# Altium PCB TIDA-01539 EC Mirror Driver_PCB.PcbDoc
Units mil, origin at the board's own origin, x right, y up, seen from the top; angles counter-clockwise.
Board outline 2800 x 1700 mil, 2 copper layers (Top Layer, Bottom Layer), stack 62 mil thick; 45 components, 15 nets, 162 pads, 47 vias.
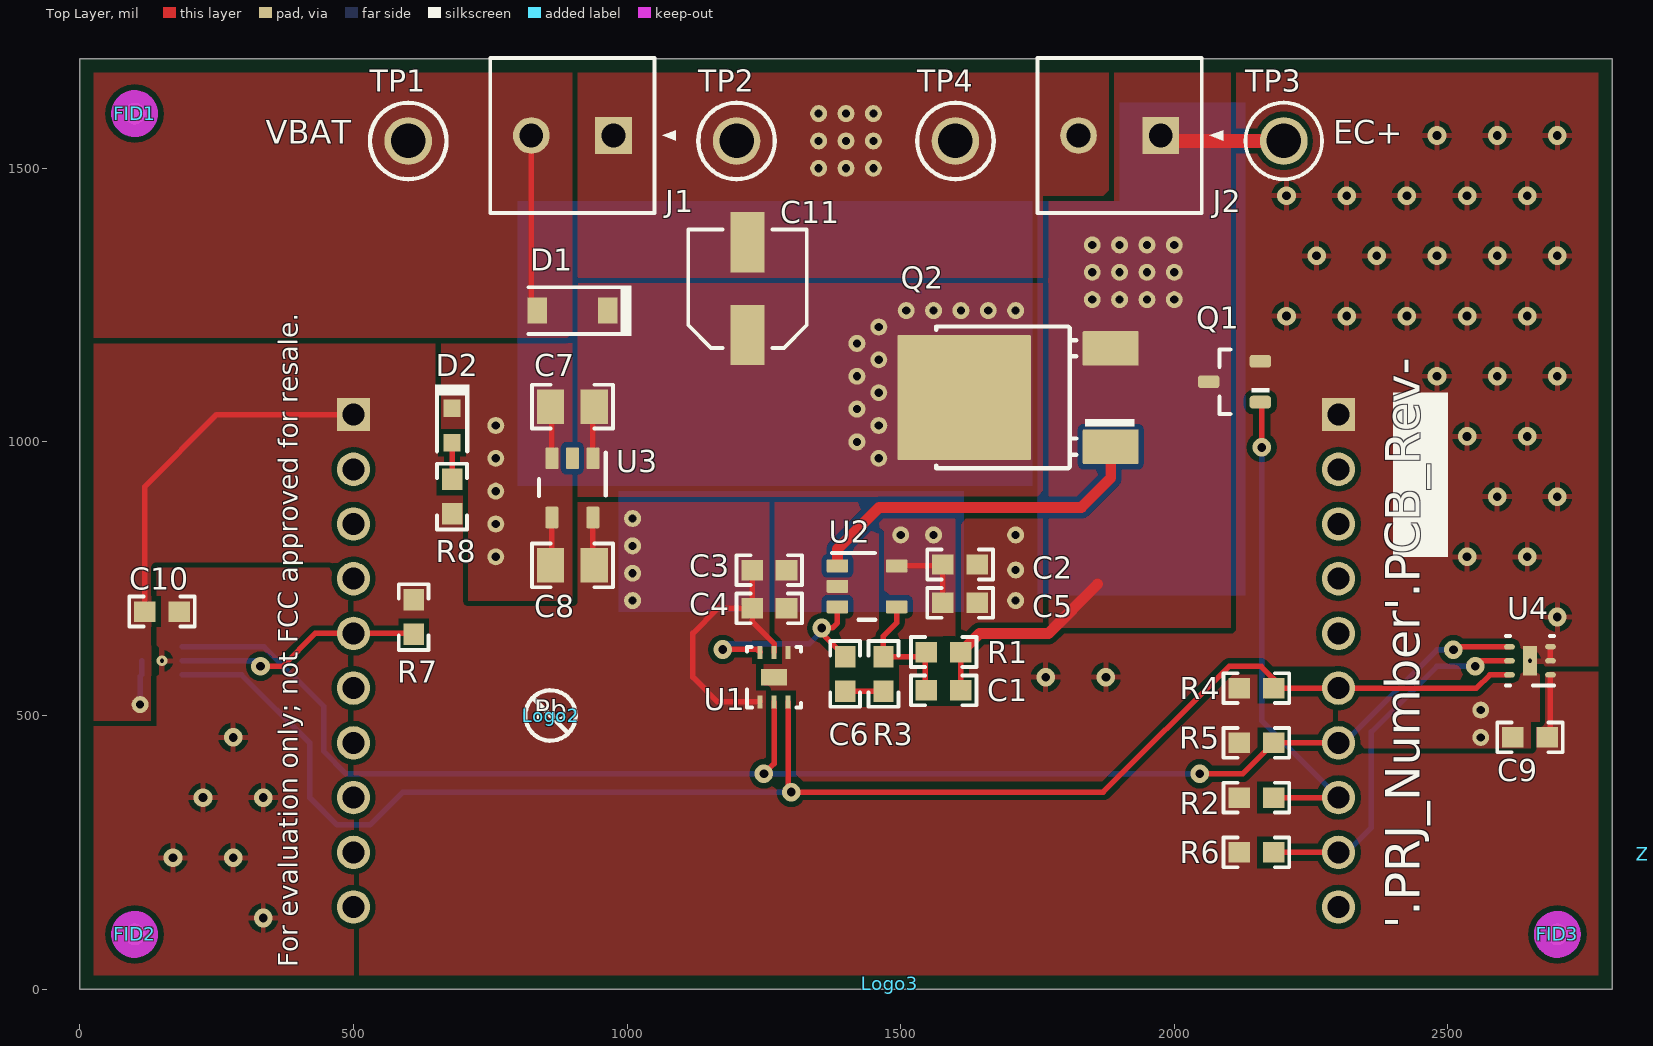
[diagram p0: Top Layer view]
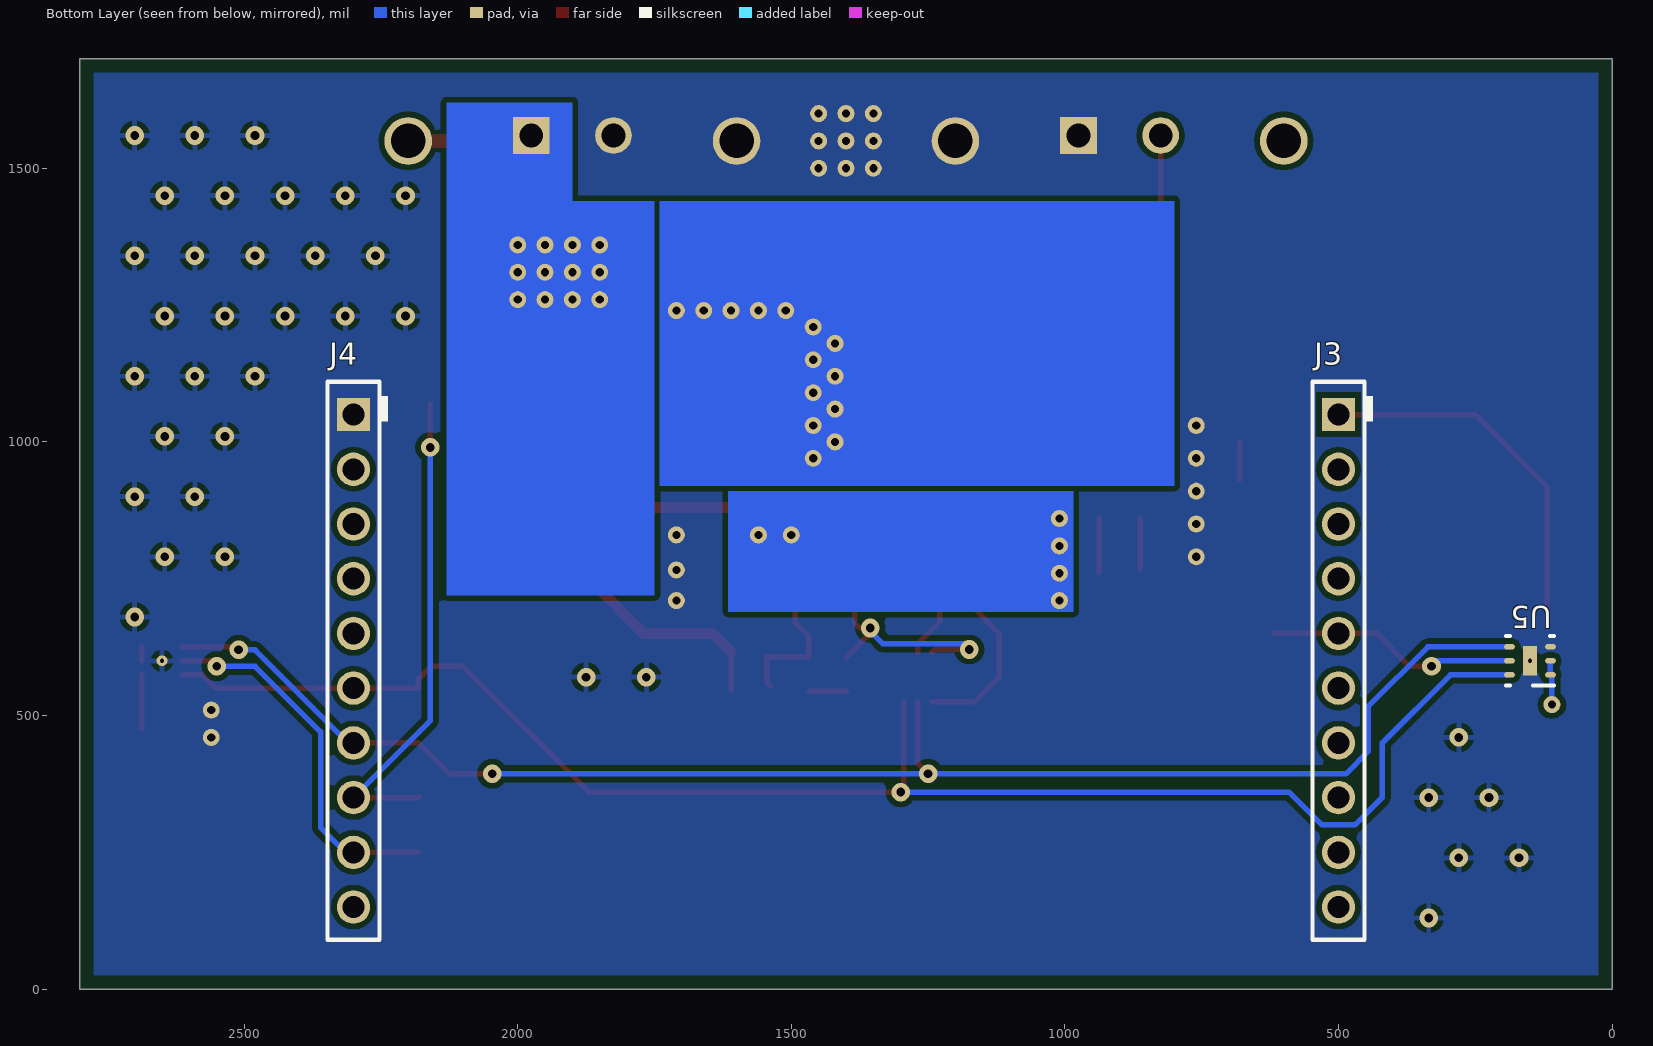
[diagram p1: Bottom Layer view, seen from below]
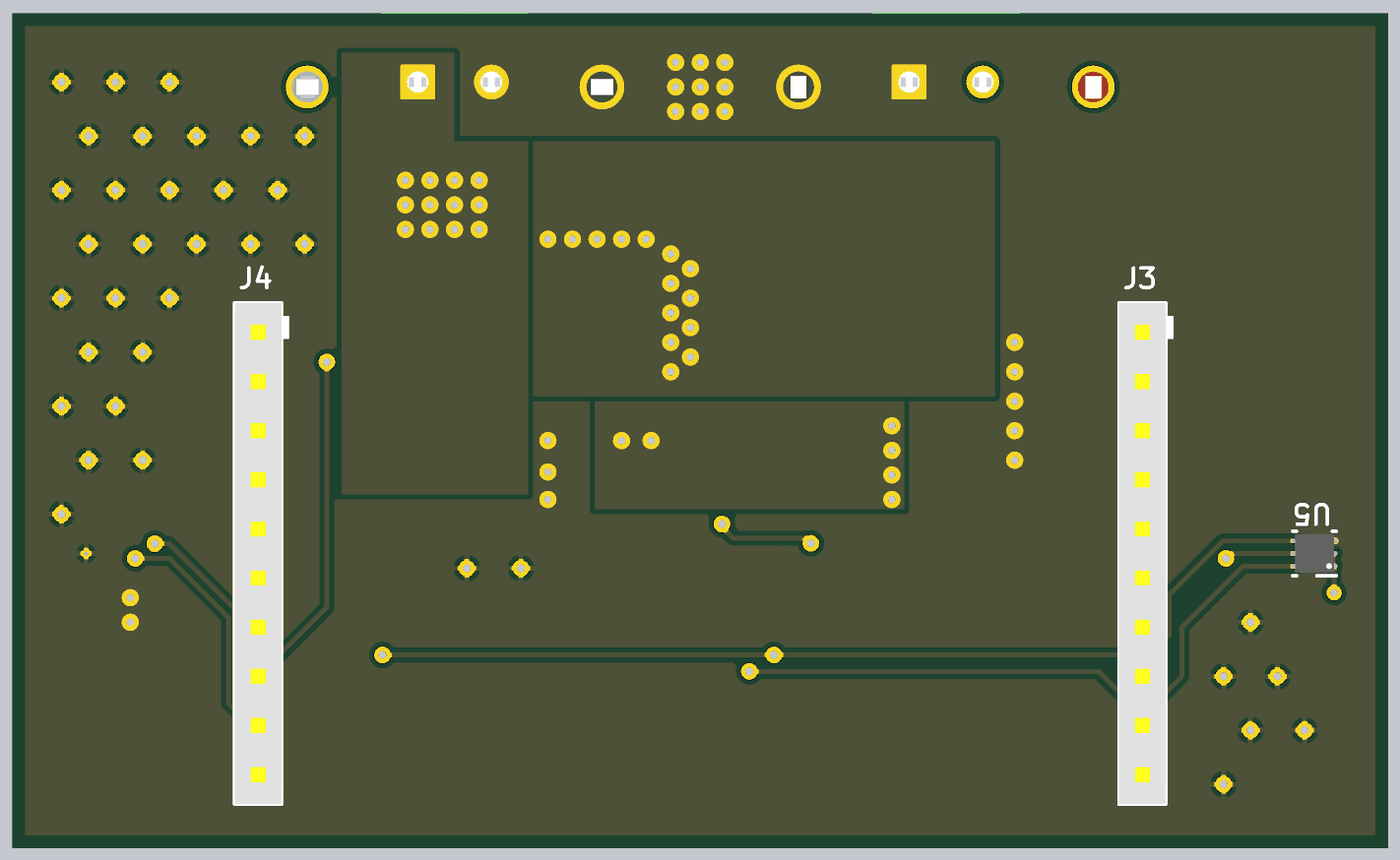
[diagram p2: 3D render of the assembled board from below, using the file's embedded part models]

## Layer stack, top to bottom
Top Solder: solder mask 0.4, Solder Resist, Dk 3.5
Top Layer: signal copper 1.4
Dielectric1: core 59.2, FR-4, Dk 4.8
Bottom Layer: signal copper 1.4
Bottom Solder: solder mask 0.4, Solder Resist, Dk 3.5

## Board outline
0,0 2800,0 2800,1700 0,1700

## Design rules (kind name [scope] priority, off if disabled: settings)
AcuteAngle [All] p1: minimum=4.50000000000000E+0001 checktracksonly=FALSE
AssemblyTestPointUsage [All] p1: valid=2
BoardOutlineClearance BoardOutlineClearance_MountingHoles [OnCopper and InComponentClass('Mounting Holes')] p1: gap=40 ignorepadtopadclearanceinfootprint=FALSE
BoardOutlineClearance BoardOutlineClearance_Poly [OnCopper and IsPoly] p2: gap=25 ignorepadtopadclearanceinfootprint=FALSE
BoardOutlineClearance [OnCopper and Not InComponentClass('Logo') and not InComponentClass('FiducialMark') and not InRegion(1000,500,4000,800) and not InPoly] p3: gap=75 ignorepadtopadclearanceinfootprint=FALSE
Clearance Clearance_Keepouts [((IsTrack Or IsArc) And Not InPoly) And IsFree and IsKeepOut vs ((IsTrack Or IsArc) And Not InPoly) And IsFree and IsKeepOut] p1: gap=0 ignorepadtopadclearanceinfootprint=FALSE
Clearance Clearance_Poly [InPolygon] p2: gap=10 ignorepadtopadclearanceinfootprint=FALSE
Clearance Clearance_FiducialMark [IsKeepOut and InComponentClass('FiducialMark') vs IsPad and InComponentClass('FiducialMark')] p3: gap=0 ignorepadtopadclearanceinfootprint=FALSE
Clearance [All] p4: gap=7.87 ignorepadtopadclearanceinfootprint=FALSE except(0: Arc-Hole Track-Hole SMDPad-Hole THPad-Hole Via-Hole Fill-Hole Poly-Hole Region-Hole Text-Hole)
ComponentClearance ComponentClearance_MountingHoles_FiducialMarks [InComponentClass('Mounting Holes') vs InComponentClass('FiducialMark')] p1: gap=50 collisioncheckmode=3 verticalgap=10 showdistances=FALSE
ComponentClearance ComponentClearance_Shunt [InComponentClass('Header') vs InComponentClass('Shunt')] p2: gap=0 collisioncheckmode=3 verticalgap=0 showdistances=FALSE
ComponentClearance ComponentClearance_Logo [InComponentClass('Logo')] p3: gap=50 collisioncheckmode=3 verticalgap=10 showdistances=FALSE
ComponentClearance ComponentClearance_ScrewToNut [(HasFootprint('NY PMS 440 0025 PH')) vs (HasFootprint('Keystone_1902C'))] p4: gap=5 collisioncheckmode=3 verticalgap=10 showdistances=FALSE
ComponentClearance ComponentClearance_MountingHoles [InComponentClass('Mounting Holes')] p5: gap=250 collisioncheckmode=3 verticalgap=100000 showdistances=FALSE
ComponentClearance ComponentClearance_SmallPassives [HasFootprint('0201*') or HasFootprint('0402*') or HasFootprint('0508') or HasFootprint('0603*') or HasFootprint('0612') or HasFootprint('0805*') or HasFootprint('0815*') or HasFootprint('0830*') or HasFootprint('1206*') or HasFootprint('1210*') or HasFootprint('1808*') or HasFootprint('1812*') or HasFootprint('1825*') or HasFootprint('2010*') or HasFootprint('2220*') or HasFootprint('2225*') or HasFootprint('2512*') or HasFootprint('2728*') or HasFootprint('3518*') vs HasFootprint('0201*') or HasFootprint('0402*') or HasFootprint('0508') or HasFootprint('0603*') or HasFootprint('0612') or HasFootprint('0805*') or HasFootprint('0815*') or HasFootprint('0830*') or HasFootprint('1206*') or HasFootprint('1210*') or HasFootprint('1808*') or HasFootprint('1812*') or HasFootprint('1825*') or HasFootprint('2010*') or HasFootprint('2220*') or HasFootprint('2225*') or HasFootprint('2512*') or HasFootprint('2728*') or HasFootprint('3518*')] p6: gap=14.96 collisioncheckmode=3 verticalgap=10 showdistances=FALSE
ComponentClearance ComponentClearance_THtoSMT [IsThruComponent vs IsSMTComponent] p7: gap=40 collisioncheckmode=3 verticalgap=30 showdistances=FALSE
ComponentClearance ComponentClearance_THtoTH [IsThruComponent vs IsThruComponent] p8: gap=30 collisioncheckmode=3 verticalgap=30 showdistances=FALSE
ComponentClearance [All] p9: gap=30 collisioncheckmode=3 verticalgap=10 showdistances=FALSE
DiffPairsRouting [All] p1: maxlimit=100 minlimit=10 mostfreqgap=10 toplayer_minwidth=15 toplayer_maxwidth=15 toplayer_prefwidth=15 bottomlayer_minwidth=15 bottomlayer_maxwidth=15 bottomlayer_prefwidth=15 maxuncoupledlength=1000
FabricationTestPointUsage TestPointUsage [All] p1: valid=2 allowmultiple=FALSE
FabricationTestpoint Testpoint [All] p1: side=3 testpointundercomponent=TRUE minsize=40 maxsize=100 preferedsize=60 minholesize=0 maxholesize=40 preferedholesize=32 testpointgrid=1 allowsidetop=TRUE allowsidebottom=TRUE usegrid=TRUE gridtolerance=0.01
FanoutControl Fanout_LCC [IsLCC] p1: bgadir=Out bgaviamode=Centered fanoutstyle=Auto fanoutdirection=Alternating viagrid=1 // Fanout_LCC (Default Rule)
FanoutControl Fanout_BGA [IsBGA] p2: bgadir=Out bgaviamode=Centered fanoutstyle=Auto fanoutdirection=Alternating viagrid=1 // Fanout_BGA (Default Rule)
FanoutControl Fanout_Default [All] p4: bgadir=Out bgaviamode=Centered fanoutstyle=Auto fanoutdirection=Alternating viagrid=1 // Fanout_Default (Default Rule)
FanoutControl Fanout_Small [(CompPinCount < 5)] p5: bgadir=Out bgaviamode=Centered fanoutstyle=Auto fanoutdirection=OutThenIn viagrid=1 // Fanout_Small (Default Rule)
HoleSize [All] p1: absolutevalues=TRUE maxlimit=251 minlimit=7.87 maxpercent=80.000 minpercent=20.000
MinimumAnnularRing MinimumAnnularRing_ThermalPadVias [IsVia and InAnyComponent] p1: minimumring=5.91
MinimumAnnularRing [All] p2: minimumring=8
MinimumSolderMaskSliver MinimumSolderMaskSliver_Logo [InComponentClass('Logo') vs InComponentClass('Logo')] p1: minsoldermaskwidth=0.7
MinimumSolderMaskSliver [All] p2: minsoldermaskwidth=3.94
PlaneConnect [All] p1: planeconnectstyle=Direct reliefexpansion=10 reliefentries=4 reliefconductorwidth=10 reliefairgap=10
PolygonConnect [All] p1: thpad.connectstyle=Direct thpad.reliefconductorwidth=10 thpad.reliefentries=4 thpad.polygonreliefangle="90 Angle" thpad.airgapwidth=10 smdpad.connectstyle=Direct smdpad.reliefconductorwidth=10 smdpad.reliefentries=4 smdpad.polygonreliefangle="90 Angle" smdpad.airgapwidth=10 via.connectstyle=Relief via.reliefconductorwidth=10 via.reliefentries=4 via.polygonreliefangle="90 Angle" via.airgapwidth=10
RoutingVias ThermalPadVias [IsVia and InAnyComponent] p1: holewidth=7.87 width=19.68 viastyle="Through Hole" minholewidth=7.87 minwidth=19.68 maxholewidth=12.99 maxwidth=23.62
RoutingVias [All] p2: holewidth=16 width=34 viastyle="Through Hole" minholewidth=7.87 minwidth=26 maxholewidth=40 maxwidth=65
SilkToBoardRegionClearance [Not ((IsComment or IsDesignator) And (Hide <> 'False')) and not InRegion(1000,500,4000,800)] p1:
SilkToSilkClearance SilkToSilkClearance_Pb-FreeLogo [(HasFootprint('Pb-Free_Overlay_Medium') OR HasFootprint('Pb-Free_Overlay_Small')) vs (HasFootprint('Pb-Free_Overlay_Medium') OR HasFootprint('Pb-Free_Overlay_Small'))] p1: silktosilkclearance=0
SilkToSilkClearance [All] p2: silktosilkclearance=4
SilkToSolderMaskClearance SilkToComponentPadClearance [(IsPad or IsFill or IsRegion) and InAnycomponent] p1: minsilkscreentomaskgap=5 clearancetoexposedcopper=TRUE
SilkToSolderMaskClearance "Silk to Solder Mask Opening" [All] p2: minsilkscreentomaskgap=4 clearancetoexposedcopper=FALSE
SolderMaskExpansion [All] p1: expansion=1.97
Width [All] p1: maxlimit=100 minlimit=6 preferedwidth=10 checkconnectedcopper=TRUE
15 further rules are at their usual default settings.

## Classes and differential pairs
component class "TIDA-01539 EC Mirror Driver_EVM_Hardware": FID1 FID2 FID3 Logo2 Logo3 ZZ1 ZZ2 ZZ3 ZZ4
component class FiducialMark: FID1 FID2 FID3
component class AssemblyNote: ZZ1 ZZ2 ZZ3 ZZ4
component class "TIDA-01539 EC Mirror Driver_Main": C1 C2 C3 C4 C5 C6 C7 C8 C9 C10 C11 D1 D2 J1 J2 J3 J4 Q1 Q2 R1 R2 R3 R4 R5 R6 R7 R8 TP1 TP2 TP3 TP4 U1 U2 U3 U4 U5

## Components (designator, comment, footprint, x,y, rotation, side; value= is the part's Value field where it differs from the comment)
C1 "0603ZC100KAT2A" 0603 1578.5,545.96 r180 top value=10pF
C2 "GRM188Z71C475KE21D" 0603 1608.5,775.96 r0 top value=4.7uF
C3 "GCM188R71C104KA37J" 0603 1259.8,765.66 r0 top value=0.1uF
C4 "GRM188Z71C475KE21D" 0603 1259.8,695.66 r0 top value=4.7uF
C5 "GCM188R71C104KA37J" 0603 1608.5,705.96 r0 top value=0.1uF
C6 "GCM188R71H472KA37D" 0603 1398.5,575.96 r90 top value=4700pF
C7 "GCM21BR71C475KA73K" 0805_HV 900,1064.53 r180 top value=4.7uF
C8 "CGA4J3X7R1E225K125AB" 0805_HV 900,774.53 r180 top value=2.2uF
C9 "GCM188R71C104KA37J" 0603 2650,460 r180 top value=0.1uF
C10 "GCM188R71C104KA37J" 0603 150,690 r0 top value=0.1uF
C11 "EEE-FK1V220R" SM_RADIAL_C 1220,1280 r90 top value=22uF
D1 "1N5819HW-7-F" SOD-123 900,1240 r180 top value=40V
D2 "150060GS75000" WL-SMCW_GREEN 680,1030 r270 top value=Green
FID1 "Fiducial" Fiducial10-20 100,1600 r0 top
FID2 "Fiducial" Fiducial10-20 100,100 r0 top
FID3 "Fiducial" Fiducial10-20 2700,100 r0 top
J1 "1727010" PhoenixConact_1727010 900,1560 r180 top
J2 "1727010" PhoenixConact_1727010 1900,1560 r180 top
J3 "SSQ-110-23-F-S" Samtec_SSQ-110-03-x-S 500,600 r270 bottom
J4 "SSQ-110-23-F-S" Samtec_SSQ-110-03-x-S 2300,600 r270 bottom
Logo2 "Pb-Free Symbol" Pb-Free_Overlay_Small 860,500 r0 top
Logo3 "FCC disclaimer" FCC_disclaimer 1480,10 r0 top
Q1 "FMMT495TA" SOT-23 2110,1110 r180 top value="150 V"
Q2 "NJVMJD122T4G" DPAK 1749.93,1081.04 r180 top value="100 V"
R1 "RT0603DRE0710K1L" 0603 1578.5,615.96 r0 top value=10.1k
R2 "RC0603FR-074K7L" 0603 2150,350 r180 top value=4.70k
R3 "CRCW0603499RFKEA" 0603 1468.5,575.96 r90 top value=499
R4 "RMCF0603FT10K0" 0603 2150,550 r180 top value=10.0k
R5 "RMCF0603FT10K0" 0603 2150,450 r180 top value=10.0k
R6 "RMCF0603FT10K0" 0603 2150,250 r180 top value=10.0k
R7 "RMCF0603FT10K0" 0603 610,680 r90 top value=10.0k
R8 "RC0603FR-07470RL" 0603 680,900 r270 top value=470
TP1 "5010" Keystone5010 600,1550 r0 top
TP2 "5011" Keystone5011 1200,1550 r0 top
TP3 "5128" Keystone5128 2200,1550 r270 top
TP4 "5011" Keystone5011 1600,1550 r270 top
U1 "DAC101C081QISD/NOPB" NGF0006A 1268.5,570 r90 top
U2 "TLV316QDBVTQ1" DBV0005A_N 1438.5,735.96 r0 top
U3 "TPS7B6933QDBVRQ1" DBV0005A_N 900,916.01 r270 top
U4 "OPT3001IDNPRQ1" DNP0006A 2650,600 r180 top
U5 "OPT3001IDNPRQ1" DNP0006A 150,600 r0 bottom
ZZ1 "This Assembly Note is for PCB labels only" AssemblyNoteLabel 185,3938 r0 top
ZZ2 "This Assembly Note will show in the PcbDoc and associated outputs" AssemblyNote 3238,246 r90 top
ZZ3 "This Assembly Note will show in the PcbDoc and associated outputs" AssemblyNote 3058,246 r90 top
ZZ4 "This Assembly Note will show in the PcbDoc and associated outputs" AssemblyNote 2878,246 r90 top

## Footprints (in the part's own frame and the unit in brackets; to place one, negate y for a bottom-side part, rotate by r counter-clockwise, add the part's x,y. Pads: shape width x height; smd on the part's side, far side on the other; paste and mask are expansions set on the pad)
0603 [mm] "0603 from SM-752 data"
  rect 1x0.95 smd: 1(-0.8,0) 2(0.8,0)
  silkscreen extent -1.52,-0.69 1.52,0.69, body extent -0.87,-0.47 0.87,0.47, height 1
0805_HV [mil] "0805 with 30mil clearance between pads"
  rect 50x63 smd: 1(-40,0) 2(40,0)
  silkscreen extent -74,-40 74,40, body extent -43,-29 43,29, height 57
AssemblyNote [mil] "Assembly Note"
AssemblyNoteLabel [mil] "Assembly Note for PCB Labels"
DBV0005A_N [mm] "SOT23, 5-Leads, Body 2.9x1.6mm, Pitch 0.95mm, Lead Span 2.8mm, IPC Medium Density"
  rrect17% 1x0.6 smd: 1(-1.375,0.95) 2(-1.375,0) 3(-1.375,-0.95) 4(1.375,-0.95) 5(1.375,0.95)
  silkscreen extent -1.63,-1.55 0.38,1.55, body extent -1.42,-1.46 1.42,1.46, height 1.09
DNP0006A [mm] "DFN-6 2x2mm"
  oval 0.5x0.25 smd: 1(-0.95,0.65) 2(-0.95,0) 3(-0.95,-0.655) 4(0.95,-0.65) 5(0.95,0) 6(0.95,0.65)
  rect 0.65x1.35 smd paste-0.5: 7(0,0)
  silkscreen extent -1.12,-1.15 1.12,1.15, body extent -1,-1 1,1, height 0.64
DPAK [mm] "D-PAK, 3-Pads, Body 6.22x6.73mm (max), TO-252AA using nominal STEP model"
  rrect6% 2.6x1.6 smd: 1(-3.4,2.28) 3(-3.4,-2.28)
  rrect2% 6.2x5.8 smd paste-2.9: 4(3.4,0)
  silkscreen extent -4.5,-3.3 4.7,3.28, body extent -3.86,-3.29 5.84,3.29, height 2.48
FCC_disclaimer [mil]
Fiducial10-20 [mm]
  round 1 smd mask+0.5: 1(0,0)
  Top Layer keep-out circle w1.178: c0,0 r0.5
Keystone5010 [mil] "Keystone Multipurpose loops"
  round 87 hole 63: 1(0,0)
  silkscreen extent -70,-70 70,70, body extent -63,-63 63,62, height 319
Keystone5011 [mil] "Keystone Multipurpose loops"
  round 87 hole 63: 1(0,0)
  silkscreen extent -70,-70 70,70, body extent -63,-63 63,62, height 319
Keystone5128 [mil] "Keystone Multipurpose loops"
  round 87 hole 63: 1(0,0)
  silkscreen extent -70,-70 70,70, body extent -63,-63 63,62, height 319
NGF0006A [mm] "TI"
  rect 0.6x0.25 smd: 1(-1.15,0.65) 2(-1.15,0) 3(-1.15,-0.65) 4(1.15,-0.65) 5(1.15,0) 6(1.15,0.65)
  rect 0.75x1.2 smd paste-0.38: 7(0,0)
  silkscreen extent -1.4,-1.25 1.4,1.25, body extent -1.3,-1.15 1.3,1.15, height 0.81
Pb-Free_Overlay_Small [mil]
  silkscreen extent -46,-46 46,46
PhoenixConact_1727010 [mm]
  rect 1.7x1.7 hole 1.1: 1(-1.905,0)
  round 1.7 hole 1.1: 2(1.905,0)
  silkscreen extent -4.8,-3.6 3.81,3.6, body extent -3.81,-3.6 3.81,3.7, height 8.52
Samtec_SSQ-110-03-x-S [mm] "Receptacle, 2.54mm, 10x1, TH"
  rect 1.55x1.55 hole 1.02: 1(-11.43,0)
  round 1.55 hole 1.02: 2(-8.89,0) 3(-6.35,0) 4(-3.81,0) 5(-1.27,0) 6(1.27,0) 7(3.81,0) 8(6.35,0) 9(8.89,0) 10(11.43,0)
  silkscreen extent -12.95,-1.21 12.95,1.6, body extent -12.95,-1.21 12.95,1.21, height 8.51
SM_RADIAL_C [mm] "5 x 5.8mm:  Panasonic C"
  rect 2.8x1.6 smd: 1(-2.15,0) 2(2.15,0)
  silkscreen extent -2.75,-2.75 2.75,2.75, body extent -2.75,-2.75 2.75,2.75, height 6.1
SOD-123 [mm] "On Semi recommended land pattern"
  rect 0.915x1.22 smd: 1(-1.637,0) 2(1.637,0)
  silkscreen extent -2.74,-1.17 2.03,1.17, body extent -1.93,-0.9 1.93,0.9, height 1.35
SOT-23 [mm] "SOT23, 3-Leads, Body 2.9x1.3mm, Pitch 0.95mm, Lead Span 2.5mm, IPC Medium Density"
  rrect50% 1x0.6 smd: 1(-1.2,0.95) 2(-1.2,-0.95) 3(1.2,0)
  silkscreen extent -1.62,-1.5 0.7,1.5, body extent -1.16,-1.45 1.21,1.45, height 1
WL-SMCW_GREEN [mm] "WURTH"
  rect 0.8x0.8 smd: 1(-0.8,0) 2(0.8,0)
  silkscreen extent -1.9,-0.8 1.2,0.8, body extent -0.85,-0.45 0.85,0.45, height 0.8

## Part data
C1: library part CMP-0006811-2, "CAP, CERM, 10 pF, 10 V, +/- 10%, X7R, 0603", Cap_Case=0603, Manufacturer=AVX, Supplier Part Number 1=0603ZC100KAT2A-ND, TempCo=X7R, Tolerance_%=10%, Value1=Unknown, Value2=10V, ValueDisplayed=10pF
C2 C4: library part CMP-0064936-2, "CAP, CERM, 4.7 uF, 16 V,+/- 10%, X7R, 0603", Cap_Case=0603, Manufacturer=MuRata, TempCo=X7R, Tolerance_%=10%, Value1=Unknown, Value2=16V, ValueDisplayed=4.7uF
C3 C5 C9 C10: library part CMP-0007135-2, "CAP, CERM, 0.1 uF, 16 V, +/- 10%, X7R, AEC-Q200 Grade 1, 0603", Cap_Case=0603, Manufacturer=MuRata, Supplier Part Number 1=490-8015-1-ND, TempCo=X7R, Tolerance_%=10%, Value1=Unknown, Value2=16V, ValueDisplayed=0.1uF
C6: library part CMP-0007146-2, "CAP, CERM, 4700 pF, 50 V, +/- 10%, X7R, AEC-Q200 Grade 1, 0603", Cap_Case=0603, Manufacturer=MuRata, Supplier Part Number 1=490-4932-1-ND, TempCo=X7R, Tolerance_%=10%, Value1=Unknown, Value2=50V, ValueDisplayed=4700pF
C7: "CAP, CERM, 4.7 µF, 16 V, +/- 10%, X7R, AEC-Q200 Grade 1, 0805", Cap_Case=0805, Manufacturer=MuRata, Supplier Part Number 1=GCM21BR71C475KA73K-ND, TempCo=X7R, Tolerance_%=10, Value1=Unknown, Value2=16V, ValueDisplayed=4.7µF
C8: "CAP, CERM, 2.2 µF, 25 V, +/- 10%, X7R, AEC-Q200 Grade 1, 0805", Cap_Case=0805, Manufacturer=TDK, Supplier Part Number 1=445-6965-1-ND, TempCo=X7R, Tolerance_%=10, Value1=Unknown, Value2=25V, ValueDisplayed=2.2µF
C11: library part CMP-0010726-1, "CAP, AL, 22 uF, 35 V, +/- 20%, 0.7 ohm, AEC-Q200 Grade 2, SMD", Cap_Case=C, Manufacturer=Panasonic, Supplier Part Number 1=PCE3838CT-ND, Tolerance_%=20%, Value1="0.7 ohm", Value2=35V, ValueDisplayed=22uF
D1: "Diode, Schottky, 40 V, 1 A, SOD-123", Manufacturer="Diodes Inc.", Supplier Part Number 1=1N5819HW-FDICT-ND, Value1=1A, Value2=0.45V
D2: library part CMP-0002905-1, "LED, Green, SMD", Color=Green, Manufacturer="Wurth Elektronik", Supplier Part Number 1=732-4971-1-ND, Value1=W, Value2=3.2V
FID1 FID2 FID3: "Fiducial mark.  There is nothing to buy or mount.", Manufacturer=N/A
J1 J2: "Conn Term Block, 2POS, 3.81mm, TH", Manufacturer="Phoenix Contact", Supplier Part Number 1=277-1947-ND
J3 J4: library part CMP-0055680-1, "Receptacle, 2.54mm, 10x1, Gold, TH", Color=Black, Current_A=6.3A, Manufacturer=Samtec, Supplier Part Number 1=84Y3838
Logo2: library part Pb-Free
Logo3: library part FCC_disclaimer, "FCC_disclaimer"
Q1: library part CMP-0074710-1, "Transistor, NPN, 150 V, 1 A, AEC-Q101, SOT-23", Manufacturer="Diodes Inc.", Supplier Part Number 1=FMMT495CT-ND, Value1="1 A", Value2=300.0
Q2: library part CMP-0077549-1, "Transistor, NPN, 100 V, 8 A, AEC-Q101, DPAK", Manufacturer="ON Semiconductor", Supplier Part Number 1=NJVMJD122T4G-VF01OSCT-ND, Value1="8 A"
R1: library part CMP-0024579-1, "RES, 10.1 k, 0.5%, 0.1 W, 0603", Manufacturer="Yageo America", Power_W=100mW, TempCo="50 ppm/C", Tolerance_%=0.5%, Value2=0.1W, Value_Code=10k1, ValueDisplayed=10.1k
R2: library part CMP-0023153-2, "RES, 4.70 k, 1%, 0.1 W, 0603", Manufacturer="Yageo America", Power_W=100mW, Supplier Part Number 1=311-4.70KHRCT-ND, TempCo="200 ppm/C", Tolerance_%=1%, Value2=0.1W, Value_Code=4k70, ValueDisplayed=4.70k
R3: library part CMP-0022446-3, "RES, 499, 1%, 0.1 W, 0603", Manufacturer=Vishay-Dale, Power_W=100mW, Supplier Part Number 1=541-499HCT-ND, TempCo="100 ppm/C", Tolerance_%=1%, Value2=0.1W, Value_Code=499R, ValueDisplayed=499
R4 R5 R6 R7: library part CMP-0023341-2, "RES, 10.0 k, 1%, 0.1 W, AEC-Q200 Grade 0, 0603", Manufacturer="Stackpole Electronics Inc", Power_W=100mW, Supplier Part Number 1=RMCF0603FT10K0CT-ND, TempCo="100 ppm/C", Tolerance_%=1%, Value2=0.1W, Value_Code=10k0, ValueDisplayed=10.0k
R8: library part CMP-0023129-2, "RES, 470, 1%, 0.1 W, 0603", Manufacturer="Yageo America", Power_W=100mW, Supplier Part Number 1=311-470HRCT-ND, TempCo="200 ppm/C", Tolerance_%=1%, Value2=0.1W, Value_Code=470R, ValueDisplayed=470
TP1: library part CMP-0055147-1, "Test Point, Multipurpose, Red, TH", Color=Red, Manufacturer=Keystone, Supplier Part Number 1=36-5010-ND
TP2 TP4: library part CMP-0055148-1, "Test Point, Multipurpose, Black, TH", Color=Black, Manufacturer=Keystone, Supplier Part Number 1=36-5011-ND
TP3: library part CMP-0055159-1, "Test Point, Multipurpose, Grey, TH", Color=Grey, Manufacturer=Keystone, Supplier Part Number 1=36-5128-ND
U1: library part CMP-0080599-1, "10-Bit Micro Power Dig-to-Analog Converter, NGF0006A (WSON-6)", Alternate Manufacturer="Texas Instruments", Alternate PartNumber=DAC101C081QISDX/NOPB
U2: library part CMP-0079805-1, "10-MHz, Rail-to-Rail Input/Output, Low-Voltage, 1.8-V CMOS Operational Amplifier, DBV0005A (SOT-23-5)", Alternate Manufacturer="Texas Instruments", Alternate PartNumber=TLV316QDBVRQ1
U3: "High Voltage Ultra Low Iq - Low Drop Out Regulator, DBV0005A (SOT-23-5)", Alternate Manufacturer="Texas Instruments"
U4 U5: library part CMP-0074867-1, "Ambient Light Sensor (ALS), DNP0006A (USON-6)", Alternate Manufacturer="Texas Instruments", Alternate PartNumber=OPT3001IDNPTQ1
ZZ1: library part AssemblyNoteLabel
ZZ2 ZZ3 ZZ4: library part AssemblyNote

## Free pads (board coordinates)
  round 31 hole 15: 1(110,520) 1(760,790) 1(760,850) 1(760,910) 1(760,970) 1(760,1030) 1(1010,710) 1(1010,760) 1(1010,810) 1(1010,860) 1(1350,1500) 1(1350,1550) 1(1350,1600) 1(1400,1500) 1(1400,1550) 1(1400,1600) 1(1420,1000) 1(1420,1060) 1(1420,1120) 1(1420,1180) 1(1450,1500) 1(1450,1550) 1(1450,1600) 1(1460,970) 1(1460,1030) 1(1460,1090) 1(1460,1150) 1(1460,1210) 1(1500,830) 1(1510,1240) 1(1560,830) 1(1560,1240) 1(1610,1240) 1(1660,1240) 1(1710,710) 1(1710,766) 1(1710,830) 1(1710,1240) 1(1850,1260) 1(1850,1310) 1(1850,1360) 1(1900,1260) 1(1900,1310) 1(1900,1360) 1(1950,1260) 1(1950,1310) 1(1950,1360) 1(2000,1260) 1(2000,1310) 1(2000,1360) 1(2560,460) 1(2560,510)

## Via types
v1: diameter 34, hole 16, Top Layer to Bottom Layer, 45 vias
v2: diameter 19.68, hole 7.87, Top Layer to Bottom Layer, 2 vias

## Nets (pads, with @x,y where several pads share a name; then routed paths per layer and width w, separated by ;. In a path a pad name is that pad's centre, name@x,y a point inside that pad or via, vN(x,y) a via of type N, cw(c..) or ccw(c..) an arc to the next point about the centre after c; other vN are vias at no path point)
DACOUT: C6.2 U1.6 U2.3 | length 402.9
  Top Layer w10: v1(1174.72,620.68) 1237.51,620.68 U1.6 ; U2.3 1384.37,669.29 1375.08,660 v1(1355.83,660) 1355.83,650.13 C6.2
  Bottom Layer w10: v1@1173.23,624.74 1179.53,631.04 1332.69,631.04 1355.83,654.17 v1(1355.83,660)
DISC: J4.8 Q1.1 R2.1 | length 898.5
  Top Layer w10: v1(2160,990) Q1.1@2160,1069.84 ; R2.1@2180,351.5 R2.1 J4.8
  Bottom Layer w10: v1(2160,990) 2160,490 J4.8
"EC +": C1.1 J2.1 pad.1@1850,1260 pad.1@1850,1310 pad.1@1850,1360 pad.1@1900,1260 pad.1@1900,1310 pad.1@1900,1360 pad.1@1950,1260 pad.1@1950,1310 pad.1@1950,1360 pad.1@2000,1260 pad.1@2000,1310 pad.1@2000,1360 Q1.3 Q2.3 R1.2 TP3.1 | length 600.5
  Top Layer w10: C1.1 R1.2
  Top Layer w20: R1.2 1644.04,650 1770,650 1860,740
  Top Layer w25: J2.1 1985,1550 TP3.1
GND: C2.2 C3.2 C4.2 C5.2 C7.2 C8.2 C9.2 C10.2 C11.2 D2.1 J1.1 J2.2 J4.1 pad.1@760,790 pad.1@760,850 pad.1@760,910 pad.1@760,970 pad.1@760,1030 pad.1@1350,1500 pad.1@1350,1550 pad.1@1350,1600 pad.1@1400,1500 pad.1@1400,1550 pad.1@1400,1600 pad.1@1450,1500 pad.1@1450,1550 pad.1@1450,1600 pad.1@1710,710 pad.1@1710,766 pad.1@1710,830 pad.1@2560,460 pad.1@2560,510 Q1.2 TP2.1 TP4.1 U1.4 U1.7 U2.2 U3.3 U3.4 U4.2 U4.3 U4.7 U5.3 U5.7 | length 206.5
  Top Layer w10: C8.2@862.6,767.41 U3.4 ; U3.3 C7.2@862.6,1056.41 ; U4.2 U4.3
  other v1: 335,130 170,240 280,240 225,350 335,350 280,460 1765,570 1875,570 2700,680 2535,790 2645,790 2590,900 2700,900 2535,1010 2645,1010 2480,1120 2590,1120 2700,1120 2205,1230 2315,1230 2425,1230 2535,1230 2645,1230 2260,1340 2370,1340 2480,1340 2590,1340 2700,1340 2205,1450 2315,1450 2425,1450 2535,1450 2645,1450 2480,1560 2590,1560 2700,1560
  other v2: 150,600 2650,600
NetC1_2: C1.2 R1.1 R3.2 U2.4 | length 232.6
  Top Layer w10: U2.4 1492.64,669.22 1468.5,645.09 R3.2 1544.5,607.45 1544.5,560.46 C1.2@1538.5,554.46
NetC6_1: C6.1 R3.1 | length 70
  Top Layer w10: C6.1 R3.1
NetD2_2: D2.2 R8.1 | length 67
  Top Layer w10: R8.1 D2.2
NetQ2_1: Q2.1 U2.1 | length 624.1
  Top Layer w20: U2.1 1384.37,804.37 1460,880 1830,880 1883.86,933.86 Q2.1@1883.86,973.86
OPT_B: J4.9 R6.1 U4.5 | length 684.4
  Top Layer w10: R6.1 J4.9 ; v1(2550,590) 2550,600 U4.5
  Bottom Layer w10: J4.9 2314.96,250 2360,295.04 2360,470 2480,590 v1(2550,590)
OPT_F: J3.5 R7.1 U5.5 | length 460.1
  Top Layer w10: v1(330,590) 370,590 430,650 J3.5 R7.1@618.5,650
  Bottom Layer w10: U5.5 320,600 v1(330,590)
SCL: J4.7 R5.1 U1.2 U4.4 U5.4 | length 2804.8
  Top Layer w10: v1(1250,393.39) 1268.5,411.89 U1.2 ; v1(2046.61,393.39) 2124.88,393.39 R5.1 J4.7 ; v1(2510,620) 2515.59,625.59 U4.4
  Bottom Layer w10: U5.4 336.65,625.59 445.29,516.95 445.29,434.71 486.61,393.39 v1(1250,393.39) v1(2046.61,393.39) ; J4.7 2310,450 2480,620 v1(2510,620)
SDA: J4.6 R4.1 U1.3 U4.6 U5.6 | length 2922.5
  Top Layer w10: U1.3 1294.09,364.09 1298.19,360 v1(1300,360) 1870,360 2100,590 2158.54,590 2181.5,567.05 R4.1 J4.6 2552.25,550 2576.66,574.41 U4.6
  Bottom Layer w10: U5.6 295.59,574.41 420,450 420,350 470,300 530,300 590,360 v1(1300,360)
V3p3: C2.1 C3.1 C4.1 C5.1 C8.1 C9.1 C10.1 J3.1 pad.1@110,520 pad.1@1010,710 pad.1@1010,760 pad.1@1010,810 pad.1@1010,860 pad.1@1500,830 pad.1@1560,830 R2.2 R4.2 R5.2 R6.2 R7.2 R8.2 U1.1 U1.5 U2.5 U3.5 U4.1 U5.1 U5.2 | length 1616
  Top Layer w10: C10.1 118.5,918.5 250,1050 J3.1 ; C8.1@937.4,762.21 U3.5 ; C4.1 1228.31,671.69 1268.5,631.5 U1.5 ; C4.1@1228.31,710.16 C3.1@1228.31,774.37 ; C4.1@1238.5,696.22 1166.22,696.22 1120,650 1120,570 1165.28,524.72 U1.1 ; U2.5 1574.41,773.36 C2.1 C5.1 ; C9.1@2687.4,475.91 U4.1
  Bottom Layer w10: pad.1@110,520 U5.1@110,571.82 ; U5.1 U5.2
VBAT: D1.2 J1.2 TP1.1 | length 309.7
  Top Layer w10: D1.2@825,1250.3 J1.2
VSUP: C7.1 C11.1 D1.1 pad.1@1420,1000 pad.1@1420,1060 pad.1@1420,1120 pad.1@1420,1180 pad.1@1460,970 pad.1@1460,1030 pad.1@1460,1090 pad.1@1460,1150 pad.1@1460,1210 pad.1@1510,1240 pad.1@1560,1240 pad.1@1610,1240 pad.1@1660,1240 pad.1@1710,1240 Q2.4 U3.1 | length 91.6
  Top Layer w10: C7.1@936.98,1062.03 937.1,1061.91 U3.1@937.1,970.44
pads on no net: FID1.1 FID2.1 FID3.1 J3.2 J3.3 J3.4 J3.6 J3.7 J3.8 J3.9 J3.10 J4.2 J4.3 J4.4 J4.5 J4.10 U3.2

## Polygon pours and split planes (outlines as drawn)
"EC +" on Top Layer "TOP_LAYER_EC_+_P002" (solid, remove dead copper, pour order 2): 2103.43,1680 2103.43,660 1770,660 1770,1440 1890,1440 1890,1680
VSUP on Top Layer "TOP_LAYER_VSUP_P000" (solid, remove dead copper, pour order 0): 910,1290 1760,1290 1760,900 910,900 910,1190
GND on Top Layer "TOP_LAYER_GND_P004" (solid, pour order 4): 910,1680 910,1300 1760,1300 1760,1450 1880,1450 1880,1680
VBAT on Top Layer "TOP_LAYER_VBAT_P008" (solid, remove dead copper, pour order 8): 900,1680 900,1190 20,1190 20,1680
GND on Top Layer "TOP_LAYER_GND_P010" (solid, remove dead copper, pour order 10): 900,1180 900,710 710,710 710,961.02 660,961.02 660,1180
V3p3 on Top Layer "TOP_LAYER_V3P3_P012" (solid, remove dead copper, pour order 12): 500,1180 1260,1180 1260,380 500,380
GND on Top Layer "TOP_LAYER_GND_P014" (solid, remove dead copper, pour order 14): 1250,890 1460.16,890 1460.16,380 1250,380
V3p3 on Top Layer "TOP_LAYER_V3P3_P016" (solid, remove dead copper, pour order 16): 1460,640 1600,640 1600,860 1460,860 1460,742.26
GND on Top Layer "TOP_LAYER_GND_P018" (solid, remove dead copper, pour order 18): 1610,860 1760,860 1760,640 1610,640
GND on Top Layer "TOP_LAYER_GND_P020" (solid, remove dead copper, pour order 20): 500,0 500,770 140,770 140,480 -70,480 -70,0
V3p3 on Top Layer "TOP_LAYER_V3P3_P022" (solid, remove dead copper, pour order 22): 510,1180 510,770 130,770 130,480 0,480 0,1180
GND on Top Layer "TOP_LAYER_GND_P026" (solid, remove dead copper, pour order 26): 2667.43,440 2667.43,590 2797.43,590 2797.43,1702.44 2110,1702.44 2110,660 1460.16,660 1460.16,380 1929.58,380 2092.92,590 2300,590 2300,440
V3p3 on Top Layer "TOP_LAYER_V3P3_P028" (solid, remove dead copper, pour order 28): 2800,660 2800,0 470,0 470,390 1921.71,390 2130,660
GND on Bottom Layer "BOTTOM_LAYER_GND_P032" (solid, remove dead copper, pour order 32): 1.73,1696.91 2801.73,1696.91 2801.73,-3.09 1.73,-3.09

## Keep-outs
Keep-Out Layer:
  text ".Layer_Name" at 577,-858.49 h60

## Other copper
Top Layer:
  text ".Layer_Name" at 577,-858.49 h60
Bottom Layer:
  region net V3p3: 985,910 1615,910 1615,690 985,690
  region net "EC +": 1900,1620 2130,1620 2130,720 1750,720 1750,1440 1900,1440
  region net VSUP: 800,1440 1740,1440 1740,920 800,920
  text ".Layer_Name" at 577,-858.49 h60

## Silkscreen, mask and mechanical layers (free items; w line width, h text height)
Top Overlay:
  region: 2400,1090 2400,790 2500,790 2500,1090
  text "VBAT" at 340,1530 h72.83
  text "EC+" at 2290,1530 h72.83
  text "'.PRJ_Number'.PCB_Rev-" at 2470,110 h108.27 r90
  text ".Layer_Name" at 577,-858.49 h60
Bottom Overlay:
  text ".Layer_Name" at 577,-858.49 h60
Top Paste:
  text ".Layer_Name" at 577,-858.49 h60
Bottom Paste:
  text ".Layer_Name" at 577,-858.49 h60
Top Solder:
  text ".Layer_Name" at 577,-858.49 h60
  text ".Layer_Name" at 577,-858.49 h60
Bottom Solder:
  text ".Layer_Name" at 577,-858.49 h60
Drill Guide:
  text ".Layer_Name" at 577,-858.49 h60
M1 Board Outline:
  lines w10: 0,0 0,1700 2800,1700 2800,0 0,0
  lines w30: 0,0 2800,0 2800,1700 0,1700 0,0
  text ".Layer_Name" at 577,-858.49 h60
M2 Board Dimensions:
  rectangle: 0,-275 125,-150
  rectangle: 125,-400 500,-275
  lines w7: 0,-275 1000,-275 ; 125,-400 125,-150 ; 250,-400 250,-150 ; 500,-400 500,-150 ; 750,-400 750,-150 ; 0,-400 1000,-400 1000,-150 0,-150 0,-400
  text ".Layer_Name" at 577,-858.49 h60
M3 3D STEP Top:
  text ".Layer_Name" at 577,-858.49 h60
M4 3D STEP Bottom:
  text ".Layer_Name" at 577,-858.49 h60
M5 Assembly Top:
  lines w10: -292,-930.17 6308,-930.17 ; -292,-726.83 6310,-726.83 ; -292,-523.5 -292,-1133.5 3713,-1133.5 6310,-1133.5 6310,-523.5 -291.5,-523.5 -291.5,-1133.5 1284,-1133.5 ; 2173,-1133.5 2173,-523.5 ; 3440,-726.83 3440,-523.5 ; 4280,-726.83 4280,-523.5 ; 4902,-1140 4902,-937.17
  text "COMPONENTS MARKED 'DNP' SHOULD NOT BE POPULATED." at 1153.5,-318.5 h60
  text "ASSEMBLY VARIANT:" at 1153,-434 h60
  text ".VariantName" at 2189,-434 h60
  text "PCB VIEWED FROM TOP SIDE" at -228.5,-655.67 h60
  text "BOARD #:" at 2248,-655.67 h60
  text ".PRJ_Number" at 2793.5,-655.67 h60
  text "REV:" at 3638,-655.67 h60
  text ".PCB_Rev" at 3929.5,-655.67 h60
  text "SVN REV:" at 4476,-655.67 h60
  text ".VersionControl_RevNumber" at 4982,-655.67 h60
  text "TID #:" at 2248,-859 h60
  text ".TID" at 2793.5,-859 h60
  text "PLOT NAME =" at -228.5,-1064.34 h60
  text ".plot_File_Name" at 577,-1064.34 h60
  text "GENERATED    :" at 2250,-1064.34 h60
  text ".Print_Date" at 3119.5,-1064.34 h60
  text ".Print_Time" at 3848.5,-1064.34 h60
  text "TEXAS INSTRUMENTS" at 5113,-1064.34 h60
M6 Assembly Bottom:
  lines w10: -292.5,-727.33 6309.5,-727.33 ; -290.5,-930.67 6309.5,-930.67 ; 1115.5,-1140.5 1115.5,-937.67 ; 1737.5,-727.33 1737.5,-524 ; 2577.5,-727.33 2577.5,-524 ; 3844.5,-1134 3844.5,-524 ; 4733.5,-1134 6309,-1134 6309,-524 -292.5,-524 -292.5,-1134 2304.5,-1134 6309.5,-1134 6309.5,-524
  text "COMPONENTS MARKED 'DNP' SHOULD NOT BE POPULATED." at 6102,-318 h60
  text ".VariantName" at 5058,-434 h60
  text "ASSEMBLY VARIANT:" at 6097,-434 h60
  text ".VersionControl_RevNumber" at 1035.5,-656.17 h60
  text "SVN REV:" at 1541.5,-656.17 h60
  text ".PCB_Rev" at 2088,-656.17 h60
  text "REV:" at 2379.5,-656.17 h60
  text ".PRJ_Number" at 3224,-656.17 h60
  text "BOARD #:" at 3769.5,-656.17 h60
  text "PCB VIEWED FROM BOTTOM SIDE" at 6246,-656.17 h60
  text ".TID" at 3224,-859.5 h60
  text "TID #:" at 3769.5,-859.5 h60
  text "TEXAS INSTRUMENTS" at 904.5,-1064.84 h60
  text ".Print_Time" at 2169,-1064.84 h60
  text ".Print_Date" at 2898,-1064.84 h60
  text "GENERATED    :" at 3767.5,-1064.84 h60
  text ".plot_File_Name" at 5440.5,-1064.84 h60
  text "PLOT NAME =" at 6246,-1064.84 h60
M9 Title Sheet:
  drawing of 57 lines, arcs and shapes, not listed
  text "1" at 739.84,8036.5 h70
  text "2" at 3235.5,8036.5 h70
  text "3" at 5724.84,8036.5 h70
  text "4" at 8231.51,8036.5 h70
  text "5" at 10730.5,8036.5 h70
  text "6" at 13235.5,8036.5 h70
  text "A" at -416.5,6893.5 h70
  text "A" at 14383.5,6893.5 h70
  text "B" at -416.5,4513.5 h70
  text "B" at 14383.5,4513.5 h70
  text "C" at -416.5,2138.5 h70
  text "C" at 14383.5,2138.5 h70
  text "PROJECT TITLE:" at 11343.5,277.5 h45
  text ".PRJ_Title" at 11393.5,144.17 h70
  text "DESIGNED FOR:" at 11343.5,-23.5 h45
  text ".PRJ_Customer" at 11393.5,-163.5 h70
  text "D" at -416.5,-231.5 h70
  text "D" at 14383.5,-231.5 h70
  text "FILE NAME:" at 11343.5,-323.5 h45
  text ".PCB_File_Name_No_Path" at 11393.5,-443.5 h70
  text "Texas Instruments (TI) and/or its licensors do not warrant the accuracy or completeness of this specification" at 6374,-605.34 h45
  text "ENGINEER:" at 11343.5,-613.5 h45
  text "LAYOUT BY:" at 12848.5,-613.5 h45
  text "or any information contained therein. TI and/or its licensors do not warrant that this design will meet" at 6329.01,-718 h45
  text ".PRJ_Engineer" at 11393.5,-768.49 h70
  text ".PCB_Layout" at 12899,-768.49 h70
  text "the specifications, will be suitable for your application or fit for any particular purpose, or will operate in" at 6329.01,-830.67 h45
  text ".Layer_Name" at 577,-858.49 h60
  text "ALTIUM DESIGNER VERSION:" at 12848.5,-923.5 h45
  text "an implementation. TI and/or its licensors do not warrant that the design is production worthy. You should" at 6329.01,-943.33 h45
  text "completely validate and test your design implementation to confirm the system functionality for your application." at 6374,-1056 h45
  text ".print_Scale" at 11393.5,-1056.83 h70
  text ".Application_BuildNumber" at 12899,-1056.83 h70
  text "1" at 739.84,-1263.5 h70
  text "2" at 3235.5,-1263.5 h70
  text "3" at 5724.84,-1263.5 h70
  text "4" at 8231.51,-1263.5 h70
  text "5" at 10730.5,-1263.5 h70
  text "6" at 13235.5,-1263.5 h70
M10 Fab Notes:
  drawing of 189 lines, arcs and shapes, not listed
  text "DESIGN INFORMATION" at 12382.02,6356.17 h60
  text "MIN. TRACK WIDTH:" at 11737.46,6224.05 h60
  text "8" at 12833.7,6224.05 h60
  text "MIL" at 12988.46,6224.05 h60
  text "MIN. CLEARANCE:" at 11737.46,6099.92 h60
  text "0.2" at 12773.7,6099.93 h60
  text "mm" at 12988.46,6099.92 h60
  text "MIN. VIA PAD SIZE:" at 11737.46,5975.8 h60
  text "24" at 12803.71,5975.8 h60
  text "MIL" at 12988.46,5975.8 h60
  text "0.05mm (2MIL)" at 12432.46,5845.9 h60
  text "MINIMUM ANNULAR RING" at 11408.23,5837.67 h60
  text "EXTERNAL" at 13140.46,5837.67 h60
  text "PER" at 11608.23,5727.55 h60
  text "IPC-D-275 CLASS 2 LEVEL C" at 11828.23,5727.54 h60
  text "MIL, HOLES" at 13316.46,5627.07 h60
  text "+/-" at 12924,5618.48 h60
  text "+/-" at 13778,5618.48 h60
  text "REGISTRATION TOLERANCES:" at 11408.23,5617.42 h60
  text "METAL" at 12608,5617.42 h60
  text "5" at 13184.2,5617.42 h60
  text "3" at 14017.2,5617.42 h60
  text "MIL" at 14133.46,5617.42 h60
  text "HOLE SIZE TOLERANCE (UNLESS OTHERWISE SPECIFIED):" at 11408.23,5519.1 h60
  text "+/-" at 13778,5516.23 h60
  text "3" at 14017.2,5515.17 h60
  text "MIL" at 14133.46,5515.17 h60
  text "MATERIAL:" at 11333.46,5377.52 h60
  text "FR-4 High Tg" at 12319.9,5249 h60
  text "X" at 12175.46,5241.01 h60
  text "FR-408" at 11754.46,5236.49 h60
  text "OTHER" at 13242.46,5236.49 h60
  text "62 MIL (1.6mm) +/-10%" at 12074.56,5093.46 h60
  text "X" at 11954.46,5091.01 h60
  text "THICKNESS:" at 11408.23,5085.24 h60
  text "OTHER" at 13359.46,5085.24 h60
  text "TOLERANCE:" at 11408.23,4946.92 h60
  text "X" at 12256.46,4946.92 h60
  text "ANSI IPC-6012 TYPE 3 CLASS 2" at 12434.48,4946.92 h60
  text "OTHER +/-" at 12434.46,4802.73 h60
  text "BOW & TWIST:" at 11408.23,4657.54 h60
  text "X" at 12256.46,4657.54 h60
  text "ANSI IPC-6012 TYPE 3 CLASS 2" at 12434.48,4657.54 h60
  text "OTHER +/-" at 12434.46,4510.85 h60
  text "DRILLING:" at 11333.46,4380.23 h60
  text "NC_DRILL FILES" at 13094.46,4275.04 h60
  text "REFERENCE:" at 11408.23,4271.1 h60
  text "X" at 12065.46,4271.01 h60
  text "AS SHOWN" at 12243.46,4271.1 h60
  text "X" at 12966.46,4271.1 h60
  text "OTHER" at 13392.46,4128.85 h60
  text "PTH COPPER THICKNESS:" at 11407.91,4125.32 h60
  text "X" at 12547.14,4125.32 h60
  text "20-30 um" at 12675.14,4125.32 h60
  text "BOARD FINISH:" at 11333.46,3977.73 h60
  text "SILKSCREEN:" at 11488.68,3867.6 h60
  text "X" at 12446.46,3867.6 h60
  text "TOP" at 12563.46,3867.6 h60
  text "X" at 12956.46,3867.6 h60
  text "BOTTOM" at 13074.46,3867.6 h60
  text "SILKSCREEN COLOR:" at 11488.68,3712.41 h60
  text "X" at 12445.46,3712.41 h60
  text "WHITE" at 12563.46,3712.41 h60
  text "OTHER" at 13074.46,3712.41 h60
  text "X" at 12576.46,3568.96 h60
  text "GREEN" at 12694.46,3568.96 h60
  text "OTHER" at 13312.46,3568.96 h60
  text "SOLDER RESIST COLOR:" at 11488.68,3562.1 h60
  text "X" at 12576.46,3414.71 h60
  text "MATTE" at 12694.46,3414.71 h60
  text "SEMI-GLOSS" at 13312,3414.07 h60
  text "IMMERSION GOLD (ENIG)" at 12394.46,3241.94 h60
  text "ENEPIG" at 13732,3234.72 h60
  text "SURFACE FINISH:" at 11333.46,3233.72 h60
  text "X" at 12216.46,3233.72 h60
  text "IMM. TIN/SILVER OR EQUIV" at 11663,3096.4 h60
  text "OTHER" at 13094.46,3092.47 h60
  text "ARRAY/PANEL:" at 11333.46,2937.09 h60
  text "CUT AND TRIM PER M1 BOARD OUTLINE" at 12394.46,2928.87 h60
  text "N.C. ROUTE" at 12394.46,2792.9 h60
  text "X" at 13082.46,2792.9 h60
  text "V. SCORE" at 13260.46,2792.9 h60
  text "CERTIFICATION:" at 11333.46,2663.77 h60
  text "MATERIALS AND WORKMANSHIP FOR ALL PCBS" at 12058.46,2663.77 h60
  text "TO MEET OR EXCEED THE REQUIREMENTS OF:" at 12058.46,2569.71 h60
  text "X" at 11695.97,2441.08 h60
  text "ANSI IPC-A-600F CLASS ->" at 11823.96,2441.08 h60
  text "X" at 13471.97,2441.08 h60
  text "2" at 13581.96,2441.08 h60
  text "1" at 13266.96,2439.58 h60
  text "3" at 13935.96,2439.58 h60
  text "X" at 12507.97,2293.39 h60
  text "RoHS" at 12635.96,2293.39 h60
  text "OTHER" at 13280.36,2293.39 h60
  text "PER ORDER" at 13677.42,2293.39 h60
  text "ALL BOARDS MUST MEET OR EXCEED UL94-V0 REQUIREMENTS." at 11361,2139.57 h60
  text "PCB MUST BEAR THE UL94V-0 UL REGISTERED MATERIAL ID NUMBER" at 11361,2023.5 h60
  text "ADDITIONAL REQUIREMENTS:" at 11333.46,1854.08 h60
  text "MICROSECTION:" at 11408.23,1746.95 h60
  text "YES" at 12313.96,1746.95 h60
  text "REQUIRED" at 13175.46,1602.62 h60
  text "BARE BOARD ELEC. TEST:" at 11408.23,1599.76 h60
  text "NONE" at 12713.96,1599.76 h60
  text "X" at 13057.46,1599.76 h60
  text "PER ORDER" at 13767.46,1599.76 h60
  text "XX MIL VIAS REQUIRE NON-CONDUCTIVE FILL AND PLANARIZE" at 11576.38,1394.82 h59
  text "XX MIL VIAS REQUIRE CONDUCTIVE FILL AND PLANARIZE" at 11584.38,1290.84 h60
  text "OUTER XX MIL VIAS REQUIRE 50 OHM SINGLE-ENDED IMPEDANCE" at 11583.39,1127.46 h58
  text "LAYER 2 & 3 (INNER LAYERS) XX MIL WIDE, XX MIL SPACE / TRACES REQUIRE 100 OHM DIFFERENTIAL IMPEDANCE" at 11575.39,891.74 h60
  text ".Layer_Name" at 577,-858.49 h60
M11 Gerber Information:
  lines w10: -292,-930.17 6308,-930.17 ; -292,-726.83 6310,-726.83 ; -292,-523.5 -292,-1133.5 3713,-1133.5 6310,-1133.5 6310,-523.5 -291.5,-523.5 -291.5,-1133.5 1284,-1133.5 ; 2173,-1133.5 2173,-523.5 ; 3440,-726.83 3440,-523.5 ; 4280,-726.83 4280,-523.5 ; 4902,-1140 4902,-937.17
  text "ALL ARTWORK VIEWED FROM TOP SIDE" at -228.5,-655.67 h60
  text "BOARD #:" at 2248,-655.67 h60
  text ".PRJ_Number" at 2793.5,-655.67 h60
  text "REV:" at 3638,-655.67 h60
  text ".PCB_Rev" at 3929.5,-655.67 h60
  text "SVN REV:" at 4476,-655.67 h60
  text ".VersionControl_RevNumber" at 4982,-655.67 h60
  text "LAYER NAME =" at -228.5,-858.49 h60
  text "TID #:" at 2248,-859 h60
  text ".TID" at 2793.5,-859 h60
  text "PLOT NAME =" at -228.5,-1064.34 h60
  text ".plot_File_Name" at 577,-1064.34 h60
  text "GENERATED    :" at 2250,-1064.34 h60
  text ".Print_Date" at 3119.5,-1064.34 h60
  text ".Print_Time" at 3848.5,-1064.34 h60
  text "TEXAS INSTRUMENTS" at 5113,-1064.34 h60
M12 Stackup:
  drawing of 191 lines, arcs and shapes, not listed
  text "Layer" at 9790.34,7830 h60
  text "Name" at 10200.26,7830 h60
  text "Material" at 11130,7830 h60
  text "Thickness" at 11989.77,7830 h60
  text "Constant" at 12639.6,7830 h60
  text "Board Layer Stack" at 13209.46,7830 h60
  text "1" at 9790.34,7710 h60
  text "Top Overlay" at 10200.26,7710 h60
  text "2" at 9790.34,7590 h60
  text "Top Solder" at 10200.26,7590 h60
  text "Solder Resist" at 11130,7590 h60
  text "0.40mil" at 11989.77,7590 h60
  text "3.5" at 12639.6,7590 h60
  text "3" at 9790.34,7470 h60
  text "Top Layer" at 10200.26,7470 h60
  text "Copper" at 11130,7470 h60
  text "1.40mil" at 11989.77,7470 h60
  text "4" at 9790.34,7350 h60
  text "Dielectric1" at 10200.26,7350 h60
  text "FR-4" at 11130,7350 h60
  text "59.20mil" at 11989.77,7350 h60
  text "4.8" at 12639.6,7350 h60
  text "5" at 9790.34,7230 h60
  text "Bottom Layer" at 10200.26,7230 h60
  text "Copper" at 11130,7230 h60
  text "1.40mil" at 11989.77,7230 h60
  text "6" at 9790.34,7110 h60
  text "Bottom Solder" at 10200.26,7110 h60
  text "Solder Resist" at 11130,7110 h60
  text "0.40mil" at 11989.77,7110 h60
  text "3.5" at 12639.6,7110 h60
  text "7" at 9790.34,6990 h60
  text "Bottom Overlay" at 10200.26,6990 h60
  text ".Layer_Name" at 577,-858.49 h60
M13 Component Bodies Top:
  text ".Layer_Name" at 577,-858.49 h60
M14 Component Bodies Bottom:
  text ".Layer_Name" at 577,-858.49 h60
M15 Courtyards Top:
  text ".Layer_Name" at 577,-858.49 h60
M16 Courtyards Bottom:
  text ".Layer_Name" at 577,-858.49 h60
Drill Drawing:
  circle w10: c5348.9,3103.54 r22.14
  lines w10: 5326.76,2826.81 5371.04,2826.81 5348.9,2782.53 5326.76,2826.81 ; 5326.76,2893.22 5337.83,2893.22 5348.9,2882.15 5359.97,2893.22 5371.04,2893.22 5359.97,2904.29 5371.04,2915.36 5359.97,2915.36 5348.9,2926.43 5337.83,2915.36 5326.76,2915.36 5337.83,2904.29 5326.76,2893.22 ; 5326.76,2981.77 5371.04,2981.77 5371.04,3026.05 5326.76,3026.05 5326.76,2981.77 ; 5326.76,3192.09 5337.83,3192.09 5337.83,3181.02 5359.97,3181.02 5359.97,3192.09 5371.04,3192.09 5371.04,3214.23 5359.97,3214.23 5359.97,3225.3 5337.83,3225.3 5337.83,3214.23 5326.76,3214.23 5326.76,3192.09 ; 5326.76,3280.64 5348.9,3291.71 5371.04,3280.64 5359.97,3302.78 5371.04,3324.92 5348.9,3313.85 5326.76,3324.92 5337.83,3302.78 5326.76,3280.64
  lines w12: 5286,2752.64 8398.94,2752.64 ; 5286,3350.38 8398.94,3350.38 ; 5601.63,2653.02 5601.63,3450 ; 5918.82,2653.02 5918.82,3450 ; 6540.56,2653.02 6540.56,3450 ; 6784.88,2653.02 6784.88,3450 ; 7145.22,2653.02 7145.22,3450 ; 7854.73,2653.02 7854.73,3450 ; 5286,2653.02 8398.94,2653.02 8398.94,3450 5286,3450 5286,2653.02
  text "Symbol" at 5345.77,3380.26 h72
  text "Quantity" at 5631.52,3380.26 h72
  text "Finished Hole Size" at 5948.7,3380.26 h72
  text "Plated" at 6570.45,3380.26 h72
  text "Hole Type" at 6814.77,3380.26 h72
  text "Drill Layer Pair" at 7175.11,3380.26 h72
  text "Hole Tolerance" at 7884.62,3380.26 h72
  text "2" at 5631.52,3280.64 h60
  text "7.87mil (0.200mm)" at 5948.7,3280.64 h60
  text "PTH" at 6570.45,3280.64 h60
  text "Round" at 6814.77,3280.64 h60
  text "Top Layer - Bottom Layer" at 7175.11,3280.64 h60
  text "52" at 5631.52,3181.02 h60
  text "15.00mil (0.381mm)" at 5948.7,3181.02 h60
  text "PTH" at 6570.45,3181.02 h60
  text "Round" at 6814.77,3181.02 h60
  text "Top Layer - Bottom Layer" at 7175.11,3181.02 h60
  text "45" at 5631.52,3081.4 h60
  text "16.00mil (0.406mm)" at 5948.7,3081.4 h60
  text "PTH" at 6570.45,3081.4 h60
  text "Round" at 6814.77,3081.4 h60
  text "Top Layer - Bottom Layer" at 7175.11,3081.4 h60
  text "20" at 5631.52,2981.77 h60
  text "40.16mil (1.020mm)" at 5948.7,2981.77 h60
  text "PTH" at 6570.45,2981.77 h60
  text "Round" at 6814.77,2981.77 h60
  text "Top Layer - Bottom Layer" at 7175.11,2981.77 h60
  text "4" at 5631.52,2882.15 h60
  text "43.31mil (1.100mm)" at 5948.7,2882.15 h60
  text "PTH" at 6570.45,2882.15 h60
  text "Round" at 6814.77,2882.15 h60
  text "Top Layer - Bottom Layer" at 7175.11,2882.15 h60
  text "4" at 5631.52,2782.53 h60
  text "63.00mil (1.600mm)" at 5948.7,2782.53 h60
  text "PTH" at 6570.45,2782.53 h60
  text "Round" at 6814.77,2782.53 h60
  text "Top Layer - Bottom Layer" at 7175.11,2782.53 h60
  text "127 Total" at 5631.52,2682.91 h60
  text ".Layer_Name" at 577,-858.49 h60
M17 Embedded Cavity:
  text ".Layer_Name" at 577,-858.49 h60
M18 Embedded Assembly:
  text ".Layer_Name" at 577,-858.49 h60
M19 Embedded Keepout:
  text ".Layer_Name" at 577,-858.49 h60

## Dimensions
0,-400 to 1000,-400 on M2 Board Dimensions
